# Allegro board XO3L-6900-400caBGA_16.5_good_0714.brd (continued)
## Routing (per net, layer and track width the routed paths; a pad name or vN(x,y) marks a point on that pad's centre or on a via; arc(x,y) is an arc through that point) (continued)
PR19D: length 13.2
  TOP w0.152: BGA.M14 v1(23.52,19.52)
  L4_SIGNAL w0.152: v1(23.52,19.52) 23.92,19.92 26.97,19.92 27.22,19.66 35.89,19.66
PR21A: length 12.2
  TOP w0.152: BGA.N16 v1(25.12,18.72)
  L4_SIGNAL w0.152: 35.89,17.32 27.32,17.32 27.11,17.52 25.76,17.52 25.53,17.76 25.53,18.31 v1(25.12,18.72)
PR21B: length 9.2
  TOP w0.152: BGA.R19 v1(27.52,16.32)
  L4_SIGNAL w0.152: 35.89,17.06 28.26,17.06 v1(27.52,16.32)
PR21C: length 8
  TOP w0.152: 35.88,15.78 28.31,15.78 28.17,15.92 BGA.T20
PR21D: length 8.9
  TOP w0.152: 35.88,15.53 27.51,15.53 BGA.T19
PR22A: length 11.1
  TOP w0.152: BGA.U20 v1(28.32,14.72)
  L3_SIGNAL w0.152: 27.02,4.72 27.02,12.86 27.93,13.77 27.93,14.32 28.32,14.72 v1(28.32,14.72)
PR22B: length 14.1
  TOP w0.152: BGA.P17 v1(25.92,17.92)
  L3_SIGNAL w0.152: v1(25.92,17.92) 26.33,17.51 26.33,13.31 26.76,12.88 26.76,4.72
PR22C: length 9.8
  TOP w0.152: BGA.T18 v1(26.72,15.52)
  L3_SIGNAL w0.152: v1(26.72,15.52) 27.29,15.52 27.46,15.69 35.86,15.69
PR22D: length 9.8
  TOP w0.152: BGA.U19 v1(27.52,14.72)
  L3_SIGNAL w0.152: v1(27.52,14.72) 27.33,14.91 27.33,15.2 27.56,15.44 35.86,15.44
PR23A: length 10.1
  TOP w0.152: BGA.V20 v1(28.32,13.92)
  L4_SIGNAL w0.152: v1(28.32,13.92) 27.31,12.91 27.31,4.8
PR23B: length 14.7
  TOP w0.152: BGA.P16 v1(25.12,17.92)
  L4_SIGNAL w0.152: 27.06,4.8 27.06,12.87 26.32,13.61 26.32,15.66 26.31,15.67 26.31,15.68 26.08,15.91 26.07,15.91 26.05,15.93 25.76,15.93 25.51,16.17 25.51,17.28 25.12,17.68 v1(25.12,17.92)
PR23C: length 14.9
  TOP w0.152: BGA.N15 v1(24.32,18.72)
  BOTTOM w0.152: 23.62,4.72 23.62,13.52 23.92,13.82 23.92,17.76 23.93,17.77 23.93,18.33 v1(24.32,18.72)
PR23D: length 14.8
  TOP w0.152: BGA.N14 v1(23.52,18.72)
  BOTTOM w0.152: v1(23.52,18.72) 23.13,18.33 23.13,13.76 23.37,13.52 23.37,4.72
PR24A: length 11.2
  TOP w0.152: BGA.R17 v1(25.92,17.12)
  L4_SIGNAL w0.152: 35.8,15.73 27.5,15.73 27.11,16.11 27.11,16.48 26.88,16.71 26.33,16.71 v1(25.92,17.12)
PR24B: length 10
  TOP w0.152: BGA.U18 v1(26.72,14.72)
  L4_SIGNAL w0.152: 35.8,15.47 27.47,15.47 v1(26.72,14.72)
PR24C: length 14
  TOP w0.152: BGA.P15 v1(24.32,17.92)
  L4_SIGNAL w0.152: v1(24.32,17.92) BGA.P15 23.92,14.5 24.18,14.24 24.18,4.8
PR24D: length 13.2
  TOP w0.152: BGA.R16 v1(25.12,17.12)
  L4_SIGNAL w0.152: v1(25.12,17.12) 24.72,16.72 24.72,14.5 24.44,14.22 24.44,4.8
PR25A: length 10.7
  TOP w0.152: BGA.V19 v1(27.52,13.92)
  BOTTOM w0.152: 26.07,4.72 26.07,13.1 26.49,13.52 27.12,13.52 v1(27.52,13.92)
PR25B: length 12.5
  TOP w0.152: BGA.T17 v1(25.92,16.32)
  BOTTOM w0.152: 25.82,4.72 25.82,13.22 26.32,13.72 26.32,15.92 v1(25.92,16.32)
PR25C: length 11.5
  TOP w0.152: BGA.U17 v1(25.92,15.52)
  L4_SIGNAL w0.152: v1(25.92,15.52) 25.53,15.13 25.53,14.4 25.61,14.32 25.61,4.8
PR25D: length 10.5
  TOP w0.152: BGA.V17 v1(25.92,14.72)
  L4_SIGNAL w0.152: 25.86,4.8 25.86,14.26 25.92,14.31 v1(25.92,14.72)
PT9A: length 8.9
  TOP w0.152: 12.33,35.88 12.33,27.51 BGA.B1
PT9B: length 8
  TOP w0.152: 12.58,35.88 12.58,28.31 12.72,28.17 BGA.A1
PT9C: length 13.1
  TOP w0.152: BGA.G7 v1(17.12,23.52)
  L4_SIGNAL w0.152: 16.94,35.84 16.94,27.32 16.72,27.1 16.72,23.92 v1(17.12,23.52)
PT9D: length 12.4
  TOP w0.152: BGA.F7 v1(17.12,24.32)
  L4_SIGNAL w0.152: 17.19,35.84 17.19,27.39 17.52,27.06 17.52,24.72 v1(17.12,24.32)
PT10A: length 8.9
  TOP w0.152: BGA.B2 13.13,27.51 13.13,35.88
PT10B: length 8
  TOP w0.152: BGA.A2 13.52,28.17 13.38,28.31 13.38,35.88
PT10C: length 11.6
  TOP w0.152: BGA.E6 v1(16.32,25.12)
  L3_SIGNAL w0.152: 15.68,35.93 15.68,27.38 15.92,27.14 15.92,25.52 v1(16.32,25.12)
PT10D: length 10.9
  TOP w0.152: BGA.D5 v1(15.52,25.92)
  L3_SIGNAL w0.152: v1(15.52,25.92) 15.12,26.32 15.12,27.12 15.43,27.43 15.43,35.93
PT11A: length 8.9
  TOP w0.152: BGA.B3 13.93,27.51 13.93,35.88
PT11B: length 8
  TOP w0.152: BGA.A3 14.32,28.17 14.18,28.31 14.18,35.88
PT11C: length 10.8
  TOP w0.152: BGA.D6 v1(16.32,25.92)
  BOTTOM w0.152: 16.2,35.86 16.2,27.23 15.92,26.95 15.92,26.32 v1(16.32,25.92)
PT11D: length 11.6
  TOP w0.152: BGA.E7 v1(17.12,25.12)
  BOTTOM w0.152: v1(17.12,25.12) 16.72,25.52 16.72,26.95 16.46,27.22 16.46,35.86
PT12A: length 8.9
  TOP w0.152: BGA.B4 14.73,27.51 14.73,35.88
PT12B: length 8
  TOP w0.152: BGA.A4 15.12,28.17 14.98,28.31 14.98,35.88
PT12C: length 9.8
  TOP w0.152: BGA.C6 v1(16.32,26.72)
  L3_SIGNAL w0.152: 16.38,35.89 16.38,27.13 16.32,27.06 v1(16.32,26.72)
PT12D: length 10.7
  TOP w0.152: BGA.D7 v1(17.12,25.92)
  L3_SIGNAL w0.152: v1(17.12,25.92) 16.72,26.32 16.72,27.05 16.64,27.13 16.64,35.89
PT13A: length 8.9
  TOP w0.152: 15.53,35.88 15.53,27.51 BGA.B5
PT13B: length 8
  TOP w0.152: BGA.A5 15.92,28.17 15.78,28.31 15.78,35.88
PT13C: length 13.2
  TOP w0.152: BGA.G8 v1(17.92,23.52)
  BOTTOM w0.152: v1(17.92,23.52) 17.52,23.92 17.52,26.9 17.79,27.17 17.79,35.88
PT13D: length 12.4
  TOP w0.152: BGA.F8 v1(17.92,24.32)
  BOTTOM w0.152: v1(17.92,24.32) 18.32,24.72 18.32,26.95 18.04,27.23 18.04,35.88
PT14A: length 8.9
  TOP w0.152: BGA.B6 16.33,27.51 16.33,35.88
PT14B: length 8
  TOP w0.152: 16.58,35.88 16.58,28.31 16.72,28.17 BGA.A6
PT14C: length 11.5
  TOP w0.152: BGA.E8 v1(17.92,25.12)
  L3_SIGNAL w0.152: 17.44,35.86 17.44,27.08 17.52,27 17.52,25.52 v1(17.92,25.12)
PT14D: length 9.7
  TOP w0.152: BGA.C7 v1(17.12,26.72)
  L3_SIGNAL w0.152: 17.18,35.86 17.18,27.06 17.12,27 v1(17.12,26.72)
PT15A: length 8.9
  TOP w0.152: BGA.B7 17.13,27.51 17.13,35.88
PT15B: length 8
  TOP w0.152: BGA.A7 17.52,28.17 17.38,28.31 17.38,35.88
PT15C: length 13.1
  TOP w0.152: BGA.G9 v1(18.72,23.52)
  L4_SIGNAL w0.152: v1(18.72,23.52) 18.32,23.92 18.32,27.1 18.55,27.33 18.55,35.84
PT15D: length 12.4
  TOP w0.152: BGA.F9 v1(18.72,24.32)
  L4_SIGNAL w0.152: v1(18.72,24.32) 19.12,24.72 19.12,27.06 18.8,27.38 18.8,35.84
PT16A: length 8.9
  TOP w0.152: BGA.B8 17.93,27.51 17.93,35.88
PT16B: length 8
  TOP w0.152: BGA.A8 18.32,28.17 18.18,28.31 18.18,35.88
PT16C: length 10.7
  TOP w0.152: BGA.D8 v1(17.92,25.92)
  L3_SIGNAL w0.152: 18.32,35.86 18.32,26.32 v1(17.92,25.92)
PT16D: length 9.7
  TOP w0.152: BGA.C8 v1(17.92,26.72)
  L3_SIGNAL w0.152: v1(17.92,26.72) 17.92,27.02 17.96,27.06 17.96,35.86
PT17A: length 8.9
  TOP w0.152: 18.73,35.88 18.73,27.51 BGA.B9
PT17B: length 8
  TOP w0.152: BGA.A9 19.12,28.17 18.98,28.31 18.98,35.88
PT17C: length 9.7
  TOP w0.152: BGA.C9 v1(18.72,26.72)
  L3_SIGNAL w0.152: v1(18.72,26.72) 18.72,27.02 18.78,27.08 18.78,35.86
PT17D: length 10.7
  TOP w0.152: BGA.D9 v1(18.72,25.92)
  L3_SIGNAL w0.152: v1(18.72,25.92) 19.12,26.32 19.12,27.03 19.03,27.11 19.03,35.86
PT18A: length 8.9
  TOP w0.152: BGA.B10 19.53,27.51 19.53,35.88
PT18B: length 8
  TOP w0.152: 19.78,35.88 19.78,28.31 19.92,28.17 BGA.A10
PT18C: length 13.2
  TOP w0.152: BGA.G10 v1(19.52,23.52)
  L4_SIGNAL w0.152: 20.26,35.84 20.26,24.93 19.93,24.6 19.93,23.93 v1(19.52,23.52)
PT18D: length 12.3
  TOP w0.152: BGA.F10 v1(19.52,24.32)
  L4_SIGNAL w0.152: 20.01,35.84 20.01,25.04 19.52,24.55 v1(19.52,24.32)
PT21A: length 8.9
  TOP w0.152: 20.33,35.88 20.33,27.51 BGA.B11
PT21B: length 8
  TOP w0.152: BGA.A11 20.72,28.17 20.58,28.31 20.58,35.88
PT21C: length 10.7
  TOP w0.152: BGA.D10 v1(19.52,25.92)
  L3_SIGNAL w0.152: 19.81,35.86 19.81,27.13 19.92,27.03 19.92,26.32 v1(19.52,25.92)
PT21D: length 9.7
  TOP w0.152: BGA.C10 v1(19.52,26.72)
  L3_SIGNAL w0.152: 19.56,35.86 19.56,27.06 19.52,27.02 v1(19.52,26.72)
PT22A: length 8
  TOP w0.152: 21.39,35.88 21.39,28.31 21.52,28.17 BGA.A12
PT22B: length 8.9
  TOP w0.152: 21.13,35.88 21.13,27.51 BGA.B12
PT22C: length 9.7
  TOP w0.152: BGA.C11 v1(21.12,26.72)
  L3_SIGNAL w0.152: v1(21.12,26.72) 21.12,27.06 21.17,27.11 21.17,35.86
PT22D: length 10.7
  TOP w0.152: BGA.D11 v1(21.12,25.92)
  L3_SIGNAL w0.152: v1(21.12,25.92) 21.52,26.32 21.52,27.03 21.42,27.12 21.42,35.86
PT25A: length 8
  TOP w0.152: 22.18,35.88 22.18,28.31 22.32,28.17 BGA.A13
PT25B: length 8.9
  TOP w0.152: BGA.B13 21.93,27.51 21.93,35.88
PT25C: length 13.2
  TOP w0.152: BGA.G11 v1(21.12,23.52)
  L3_SIGNAL w0.152: v1(21.12,23.52) 20.72,23.92 20.72,24.67 20.31,25.09 20.31,35.86
PT25D: length 12.3
  TOP w0.152: BGA.F11 v1(21.12,24.32)
  L3_SIGNAL w0.152: v1(21.12,24.32) 21.12,24.63 20.56,25.19 20.56,35.86
PT26A: length 8
  TOP w0.152: 22.98,35.88 22.98,28.31 23.12,28.17 BGA.A14
PT26B: length 8.9
  TOP w0.152: BGA.B14 22.73,27.51 22.73,35.88
PT26C: length 10.7
  TOP w0.152: BGA.D12 v1(21.92,25.92)
  L3_SIGNAL w0.152: v1(21.92,25.92) 22.32,26.32 22.32,27.03 22.24,27.1 22.24,35.86
PT26D: length 9.7
  TOP w0.152: BGA.C12 v1(21.92,26.72)
  L3_SIGNAL w0.152: v1(21.92,26.72) 21.92,27.02 21.99,27.09 21.99,35.86
PT27A: length 8
  TOP w0.152: 23.78,35.88 23.78,28.31 23.92,28.17 BGA.A15
PT27B: length 8.9
  TOP w0.152: BGA.B15 23.53,27.51 23.53,35.88
PT27C: length 9.7
  TOP w0.152: BGA.C13 v1(22.72,26.72)
  L3_SIGNAL w0.152: 22.76,35.86 22.76,27.06 22.72,27.02 v1(22.72,26.72)
PT27D: length 10.7
  TOP w0.152: BGA.D13 v1(22.72,25.92)
  L3_SIGNAL w0.152: v1(22.72,25.92) 23.12,26.32 23.12,27.03 23.01,27.13 23.01,35.86
PT28A: length 8
  TOP w0.152: 24.58,35.88 24.58,28.31 24.72,28.17 BGA.A16
PT28B: length 8.9
  TOP w0.152: 24.33,35.88 24.33,27.51 BGA.B16
PT28C: length 13.8
  TOP w0.152: BGA.G12 v1(21.92,23.52)
  L4_SIGNAL w0.152: 21.02,35.84 21.02,27.42 20.72,27.12 20.72,24.17 20.73,24.17 20.73,24.16 20.96,23.93 20.97,23.93 20.97,23.92 21.52,23.92 v1(21.92,23.52)
PT28D: length 12.3
  TOP w0.152: BGA.F12 v1(21.92,24.32)
  L4_SIGNAL w0.152: v1(21.92,24.32) 21.52,24.72 21.52,27.11 21.28,27.35 21.28,35.84
PT32A: length 8.1
  TOP w0.152: 25.38,35.98 25.38,28.31 25.52,28.17 BGA.A17
PT32B: length 8.9
  TOP w0.152: 25.13,35.88 25.13,27.51 BGA.B17
PT32C: length 9.7
  TOP w0.152: BGA.C14 v1(23.52,26.72)
  L3_SIGNAL w0.152: 23.6,35.86 23.6,27.1 23.52,27.02 v1(23.52,26.72)
PT32D: length 10.7
  TOP w0.152: BGA.D14 v1(23.52,25.92)
  L3_SIGNAL w0.152: 23.85,35.86 23.85,27.1 23.92,27.03 23.92,26.32 v1(23.52,25.92)
PT33A: length 9.8
  TOP w0.152: BGA.C15 v1(24.32,26.72)
  L3_SIGNAL w0.152: v1(24.32,26.72) 24.55,26.95 24.55,35.86
PT33B: length 9.8
  TOP w0.152: BGA.C16 v1(25.12,26.72)
  L3_SIGNAL w0.152: 24.81,35.86 24.81,27.03 v1(25.12,26.72)
PT33C: length 13.2
  TOP w0.152: BGA.G13 v1(22.72,23.52)
  L4_SIGNAL w0.152: 22.64,35.84 22.64,27.43 22.33,27.12 22.33,26.87 22.32,26.87 22.32,23.92 v1(22.72,23.52)
PT33D: length 12.3
  TOP w0.152: BGA.F13 v1(22.72,24.32)
  L4_SIGNAL w0.152: v1(22.72,24.32) 23.12,24.72 23.12,27.22 22.89,27.45 22.89,35.84
PT34A: length 8
  TOP w0.152: BGA.A18 26.32,28.17 26.18,28.31 26.18,35.88
PT34B: length 8.9
  TOP w0.152: BGA.B18 25.93,27.51 25.93,35.88
PT34C: length 11.7
  TOP w0.152: BGA.E14 v1(23.52,25.12)
  L4_SIGNAL w0.152: v1(23.52,25.12) 23.92,25.52 23.92,27.1 24.17,27.35 24.17,35.94
PT34D: length 10.9
  TOP w0.152: BGA.D15 v1(24.32,25.92)
  L4_SIGNAL w0.152: 24.42,35.94 24.42,27.34 24.72,27.04 24.72,26.32 v1(24.32,25.92)
PT35A: length 11.6
  TOP w0.152: BGA.E15 v1(24.32,25.12)
  BOTTOM w0.152: 25.01,35.88 25.01,27.17 24.73,26.88 24.73,26.87 24.72,26.86 24.72,25.52 v1(24.32,25.12)
PT35B: length 10.8
  TOP w0.152: BGA.D16 v1(25.12,25.92)
  BOTTOM w0.152: 25.27,35.88 25.27,27.13 25.51,26.88 25.51,26.86 25.53,26.85 25.53,26.33 v1(25.12,25.92)
PT35C: length 13.2
  TOP w0.152: BGA.G14 v1(23.52,23.52)
  BOTTOM w0.152: 23.38,35.86 23.38,27.22 23.12,26.96 23.12,23.92 v1(23.52,23.52)
PT35D: length 12.4
  TOP w0.152: BGA.F14 v1(23.52,24.32)
  BOTTOM w0.152: v1(23.52,24.32) 23.92,24.72 23.92,26.96 23.67,27.21 23.67,35.86
PT36A: length 8.9
  TOP w0.152: BGA.B19 27.54,27.54 27.54,28.08 27.54,28.08 27.54,35.86
PT36B: length 8
  TOP w0.152: 27.79,35.86 27.79,28.37 27.92,28.25 BGA.A20
PT36C: length 10
  TOP w0.152: BGA.C17 v1(25.92,26.72)
  L3_SIGNAL w0.152: v1(25.92,26.72) 26.12,26.92 26.12,27.14 25.71,27.55 25.71,35.92
PT36D: length 9.8
  TOP w0.152: BGA.A19 v1(26.72,27.52)
  L3_SIGNAL w0.152: v1(26.72,27.52) 26.52,27.32 26.3,27.32 25.96,27.66 25.96,35.92

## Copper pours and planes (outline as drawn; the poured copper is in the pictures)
GND on L2_GND: 4.78,35.93 4.78,4.71 35.93,4.71 35.93,35.93
VCC on L5_PWR: 31.59,21.56 22.27,21.56 22.27,18.31 21.56,18.31 21.56,18.93 21.4,19.08 20.18,19.08 19.85,18.75 19.85,18.47 19.75,18.38 19.14,18.38 19.14,18.94 19.28,19.08 19.6,19.08 19.87,19.35 19.87,19.95 19.14,19.95 19.14,20.66 20.04,20.66 20.04,22.27 20.78,22.27 20.78,31.81 31.59,31.81
VCCIO0 on L5_PWR: 20.69,22.36 20.69,31.81 9.16,31.81 9.16,22.36
VCCIO1 on L5_PWR: 22.37,21.45 22.37,18.21 21.55,18.21 21.55,9.28 31.6,9.28 31.6,21.45
VCCIO2 on L5_PWR: 21.35,18.98 20.23,18.98 19.95,18.7 19.95,18.43 19.79,18.28 18.31,18.28 18.31,18.9 18.12,19.08 17.53,19.08 17.53,9.28 21.45,9.28 21.45,18.88
VCCIO3 on L5_PWR: 9.15,9.28 17.43,9.28 17.43,19.18 18.16,19.18 18.41,18.94 18.41,18.38 19.04,18.38 19.04,18.98 19.24,19.18 19.56,19.18 19.77,19.4 19.77,19.85 19.04,19.85 19.04,20.26 9.15,20.26
VCCIO4 on L5_PWR: 9.15,21.46 19.94,21.46 19.94,20.76 19.04,20.76 19.04,20.37 9.15,20.37
VCCIO5 on L5_PWR: 9.16,22.26 19.95,22.26 19.95,21.56 9.16,21.56

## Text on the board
User.Comments: DM | ASP | 06/27/14 | DWG NO: | XO3L-69E-400caBGA | REVISION | 1.0 | SHEET | 1 | OF | XO3L-69C-400CABGA PCB BREAKOUT | LATTICE SEMICONDUCTOR CORPORATION
Ref Des/Silkscreen Top: PCB BREAKOUT | XO3L-69C-400CABGA | SEMICONDUCTOR | LATTICE | A | B | C | D | E | F | G | H | J | K | L | M | N | P | R | T | U | V | W | Y | 1 | 2 | 3 | 4 | 5 | 6 | 7 | 8 | 9 | 10 | 11 | 12 | 13 | 14 | 15 | 16 | 17 | 18 | 19 | 20
PAGE_OUTLINE: 1 | INITIAL RELEASE | MM/DD/YYYY | XXXX XXXXX | SPECIAL INSTRUCTIONS: | 1/2 CU OZ FOR INTERNAL AND EXTERNAL LAYERS | MIN BOARD THICKNESS IS 62MILS. | DESIGNED BY: | APPROVED BY: | SIGNATURES         DATE | REV | DESCRIPTION | ESCAPE VIA DRILL | TRACE WIDTH/SPACE | ESCAPE VIA PAD | ARRAY SIZE | BGA LAND OPENING | BGA LAND PAD | PACKAGE SIZE | PITCH | SIGNAL         (L4) | SIGNAL         (L3) | GND     PLANE  (L2) | POWER   PLANE  (L5) | PRIMARY SIDE   (L1) | SECONDARY SIDE (L6) | SECONDARY SILKSCREEN | SECONDARY SOLDERMASK | PRIMARY SOLDERMASK | PRIMARY SILKSCREEN | 0.152/0.102 | 0.4064 | 0.5334 | 0.4572 | 0.2540 | 17 X 17 | 20 X 20 | 0.8 | MM | DATE | 669.3x669.3 | 787.4x787.4 | 31.5 | 18.0 | 16.0 | 10.0 | 21.0 | 6/4 | MILS | APPROVED | PCB BREAKOUT DETAILS | 6 LAYER STACKUP | REVISION
DISPLAY_TOP: FIGURE | SIZE | 10.0 | ALL UNITS ARE IN MILS | SIZE MM | 0.254 | PLATED | QTY | 249 | DRILL CHART: TOP to BOTTOM
